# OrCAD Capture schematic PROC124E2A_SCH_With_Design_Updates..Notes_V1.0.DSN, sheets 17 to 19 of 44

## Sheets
17 14. SOC POWER: size C; title: SOC POWER
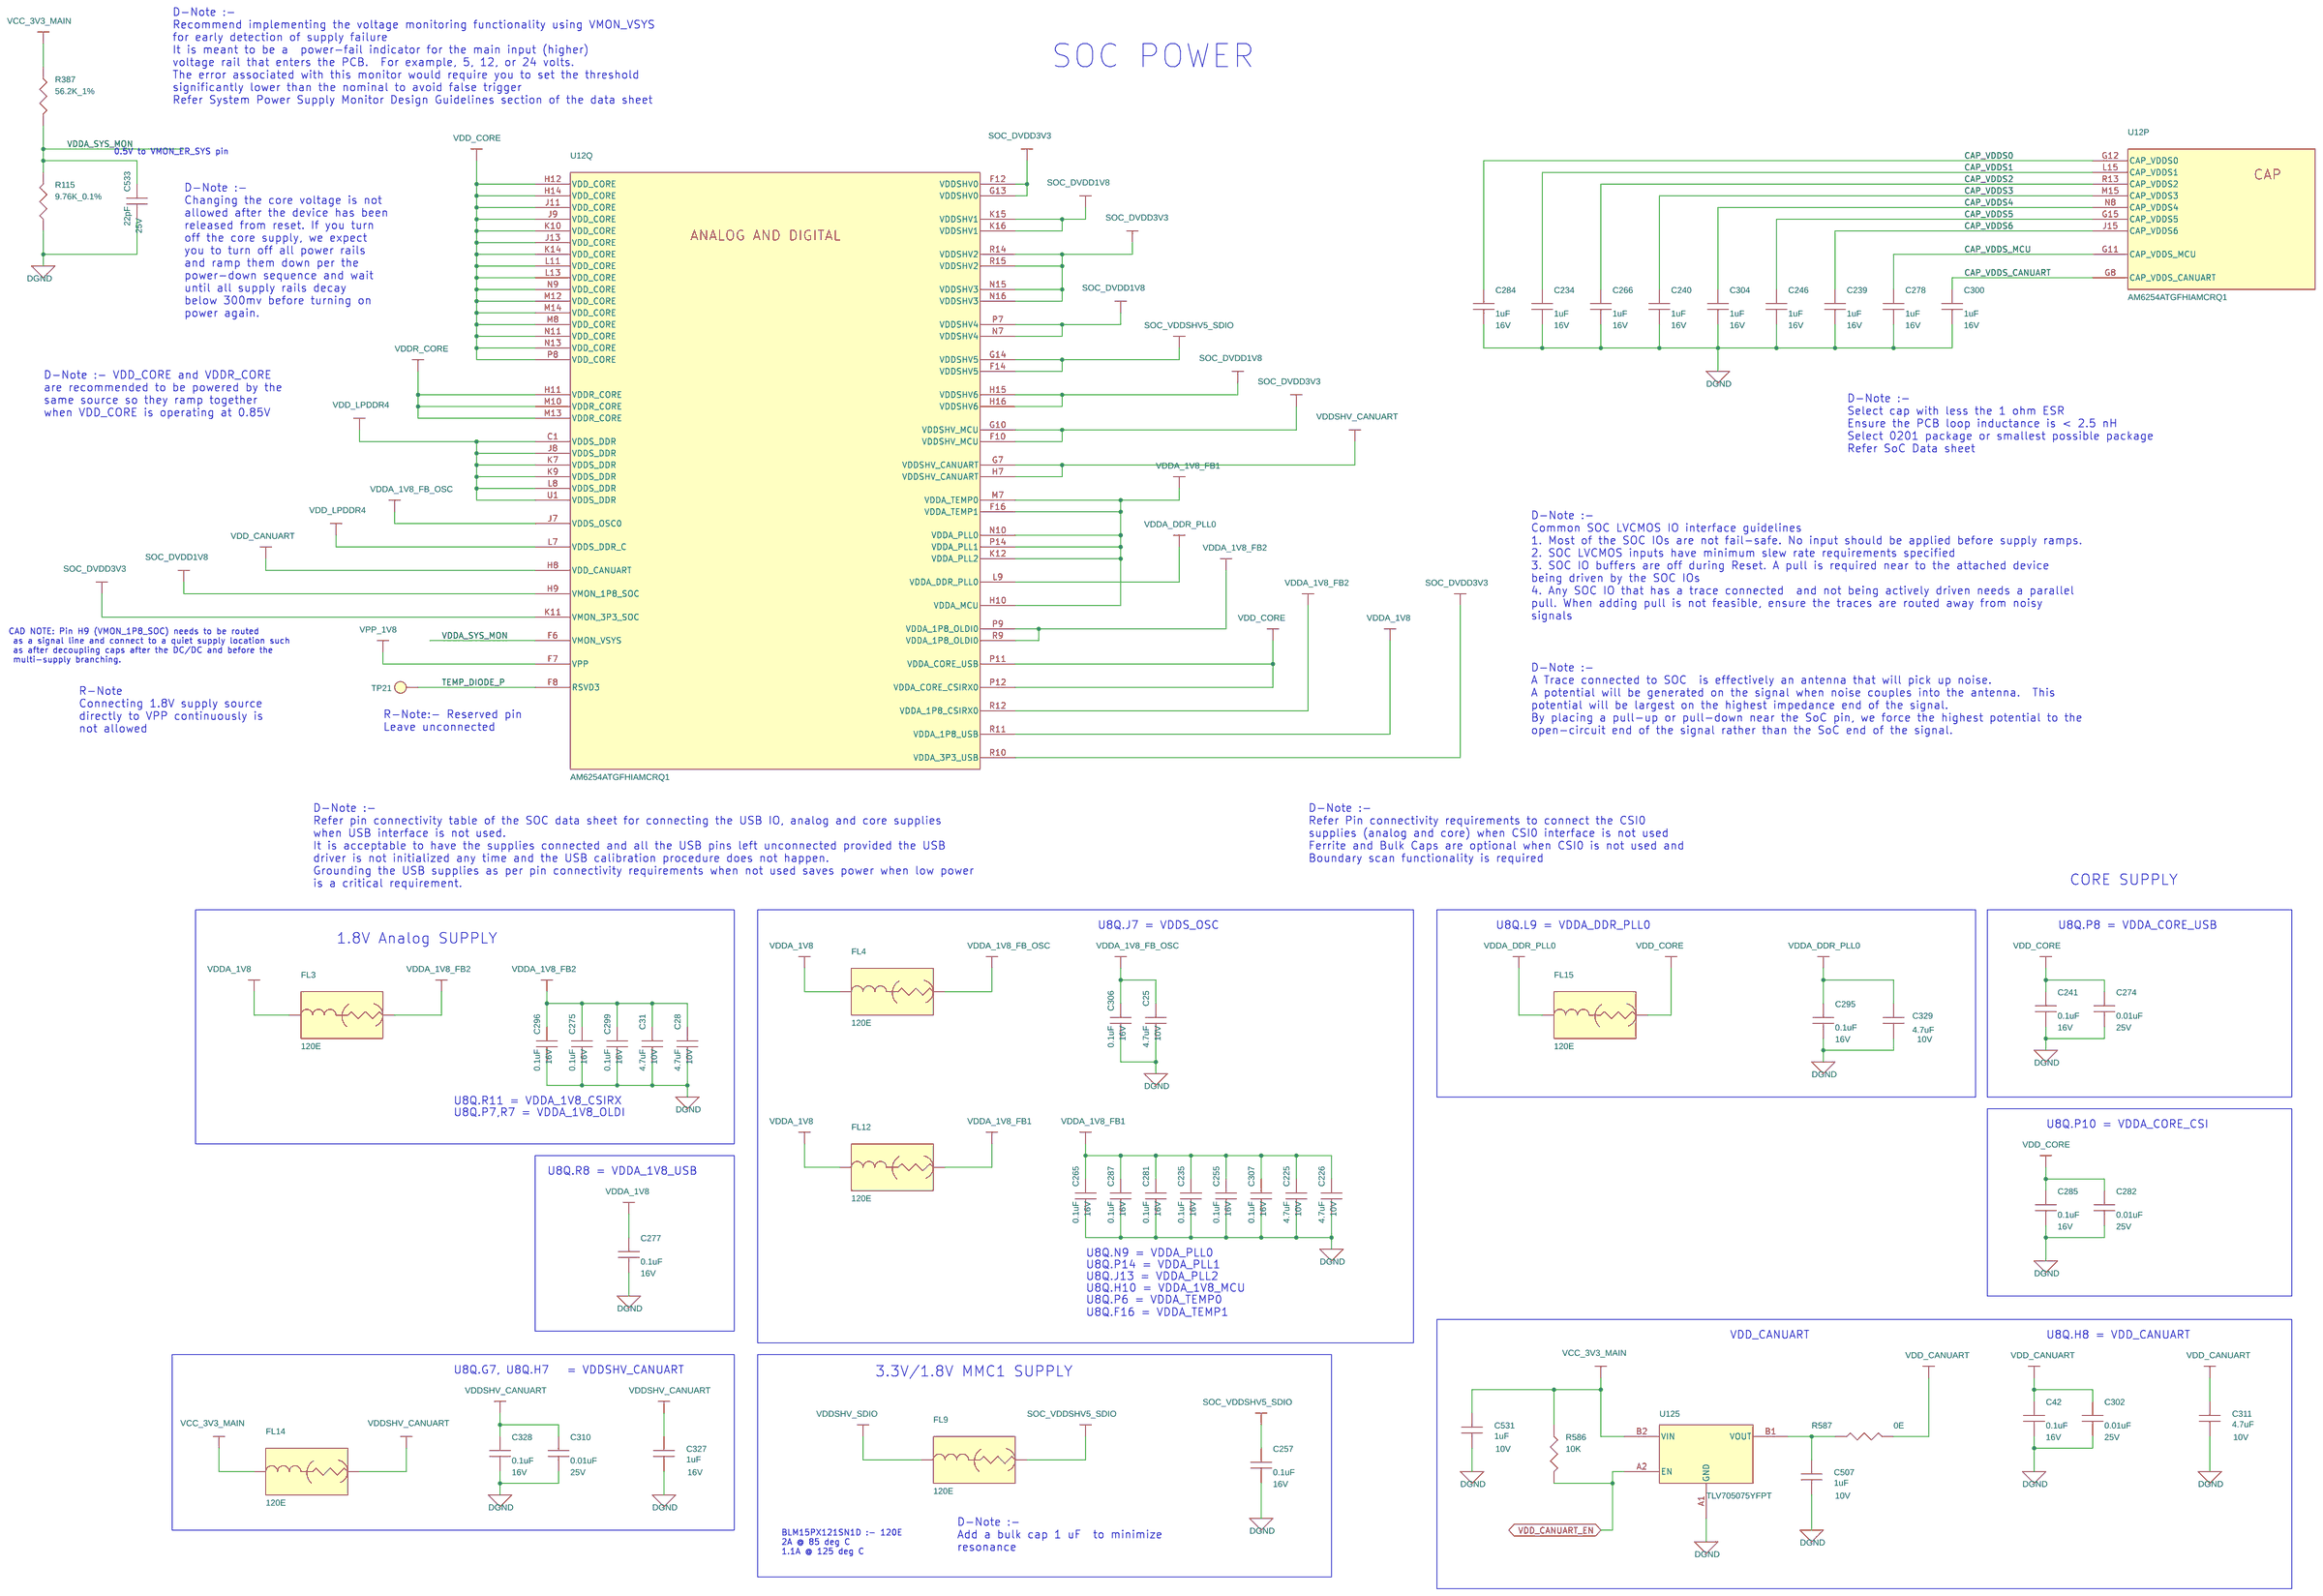
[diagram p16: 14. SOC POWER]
18 15. SOC POWER CAPS: size C; title: SOC POWER CAPS & SOC VSS
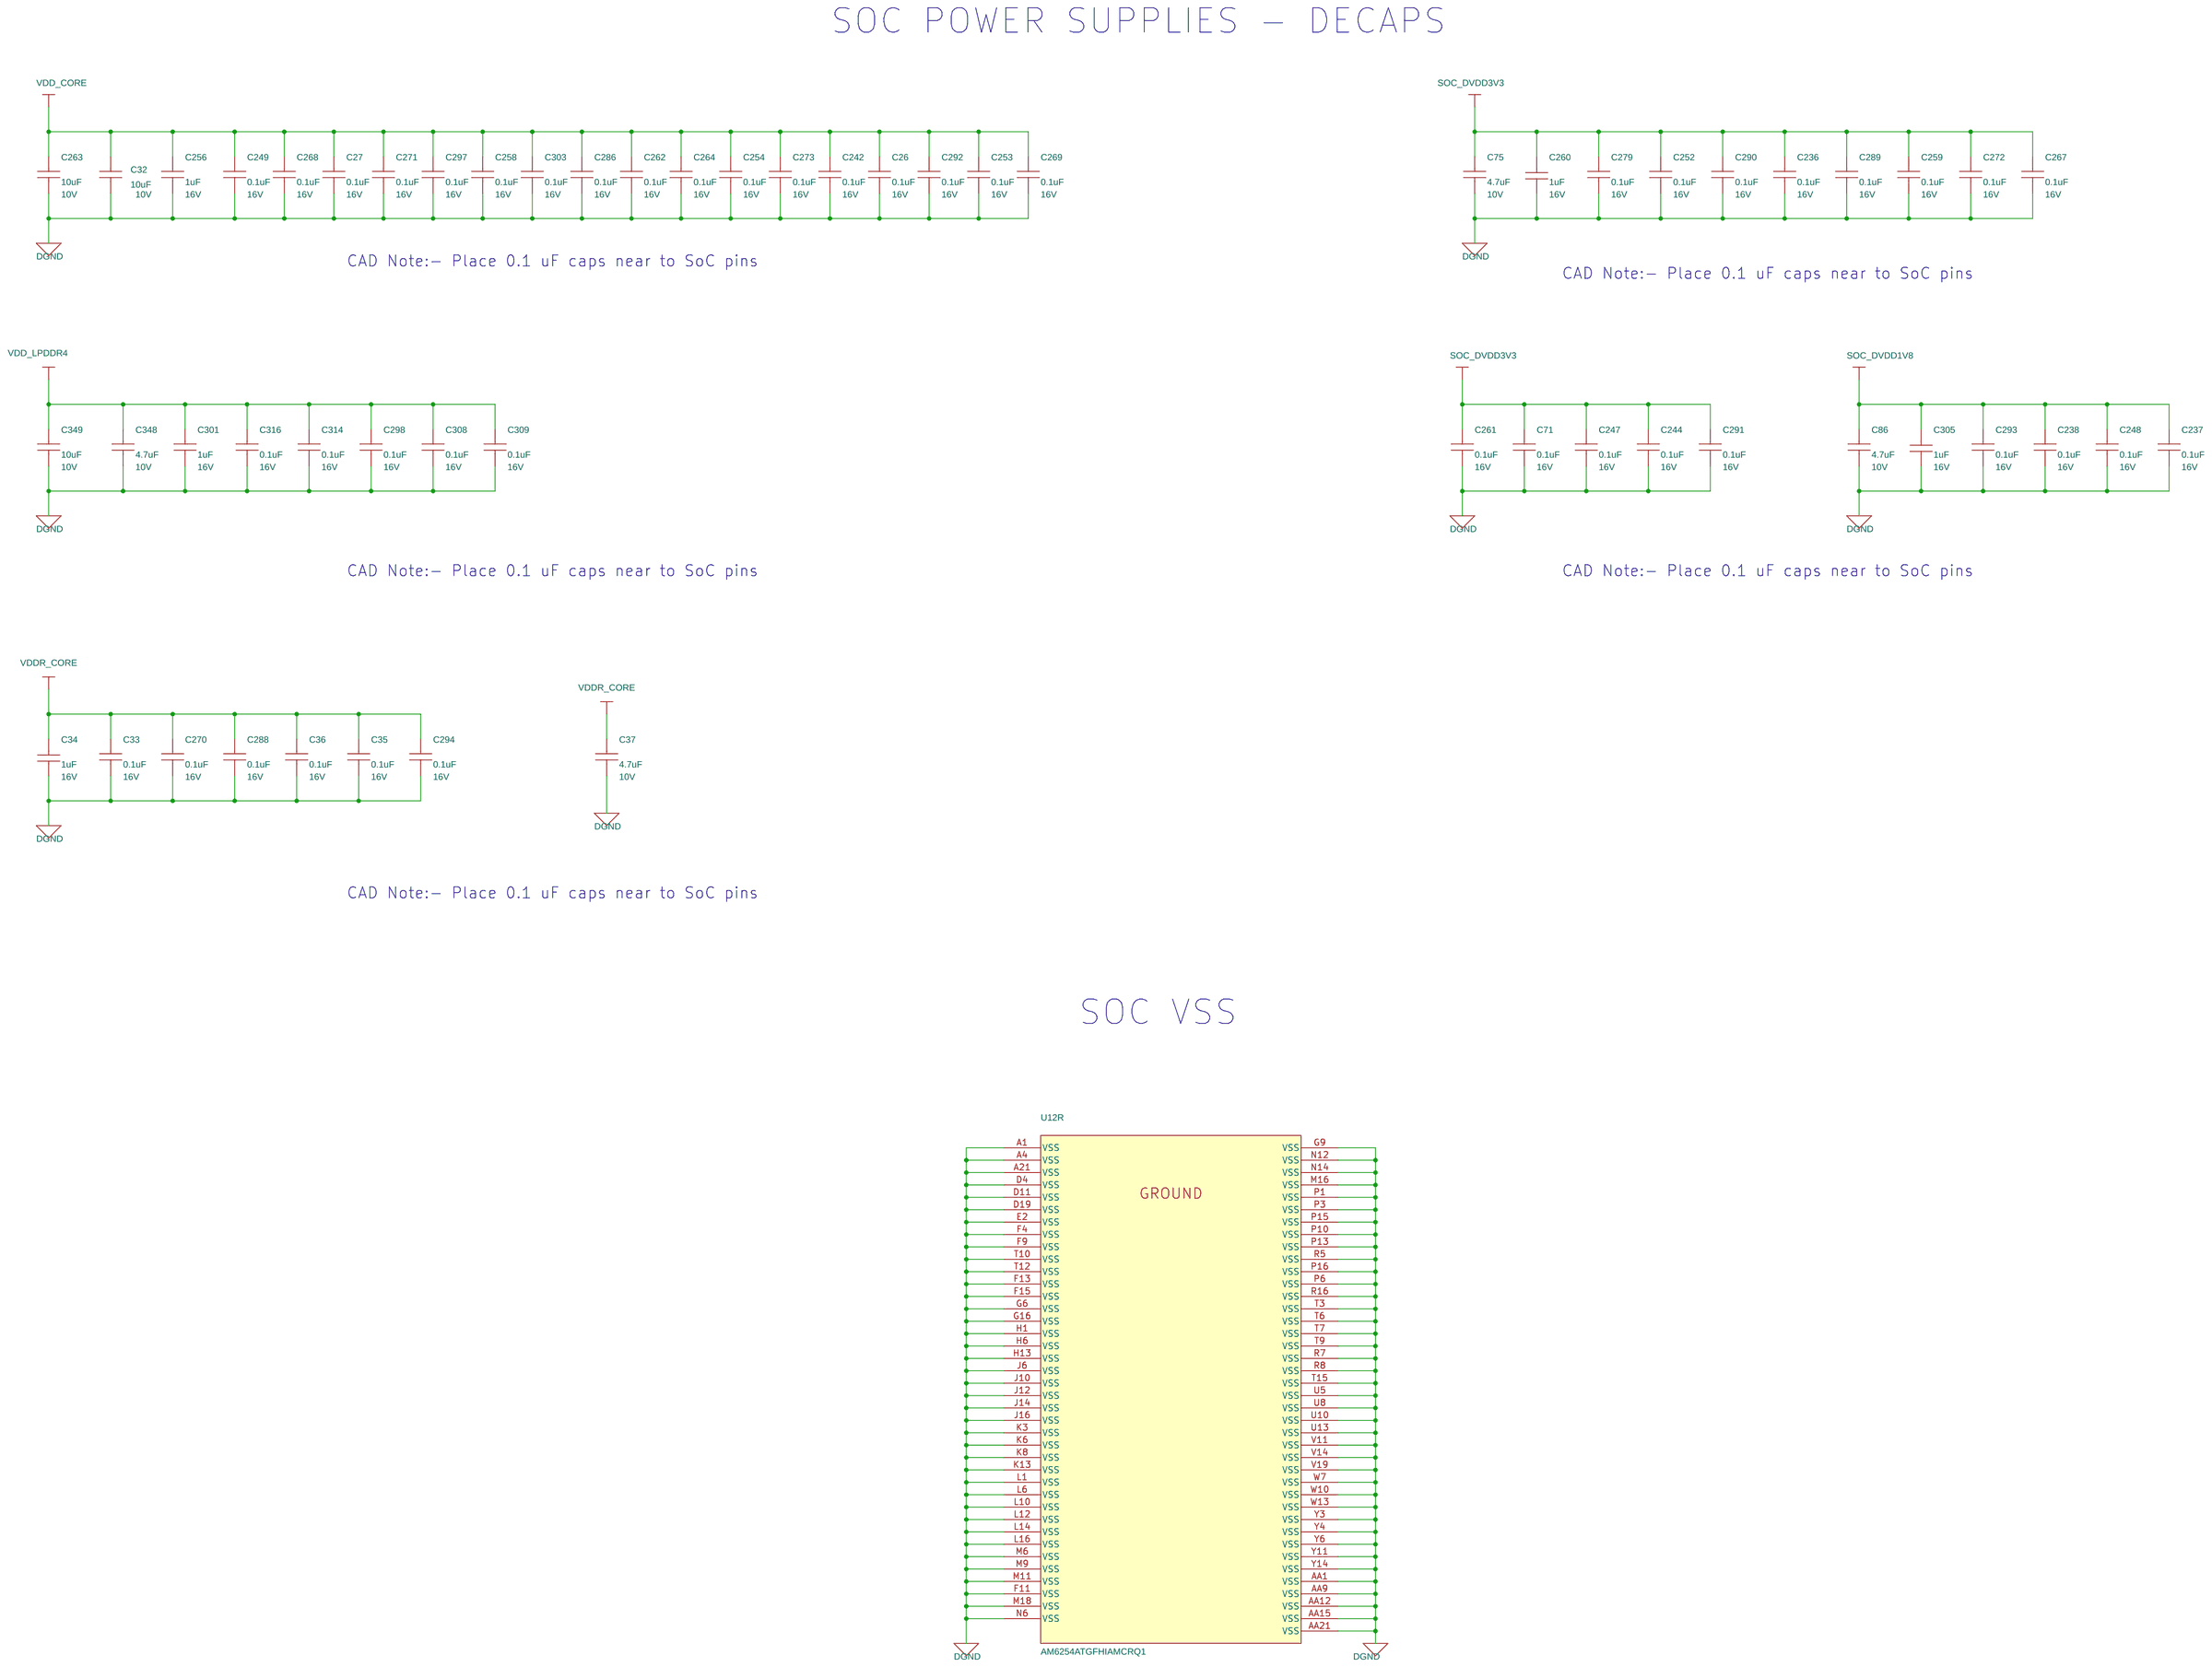
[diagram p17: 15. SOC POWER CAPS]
19 17. M.2 CONNECTOR: size C; title: M.2 CONNECTOR I/F
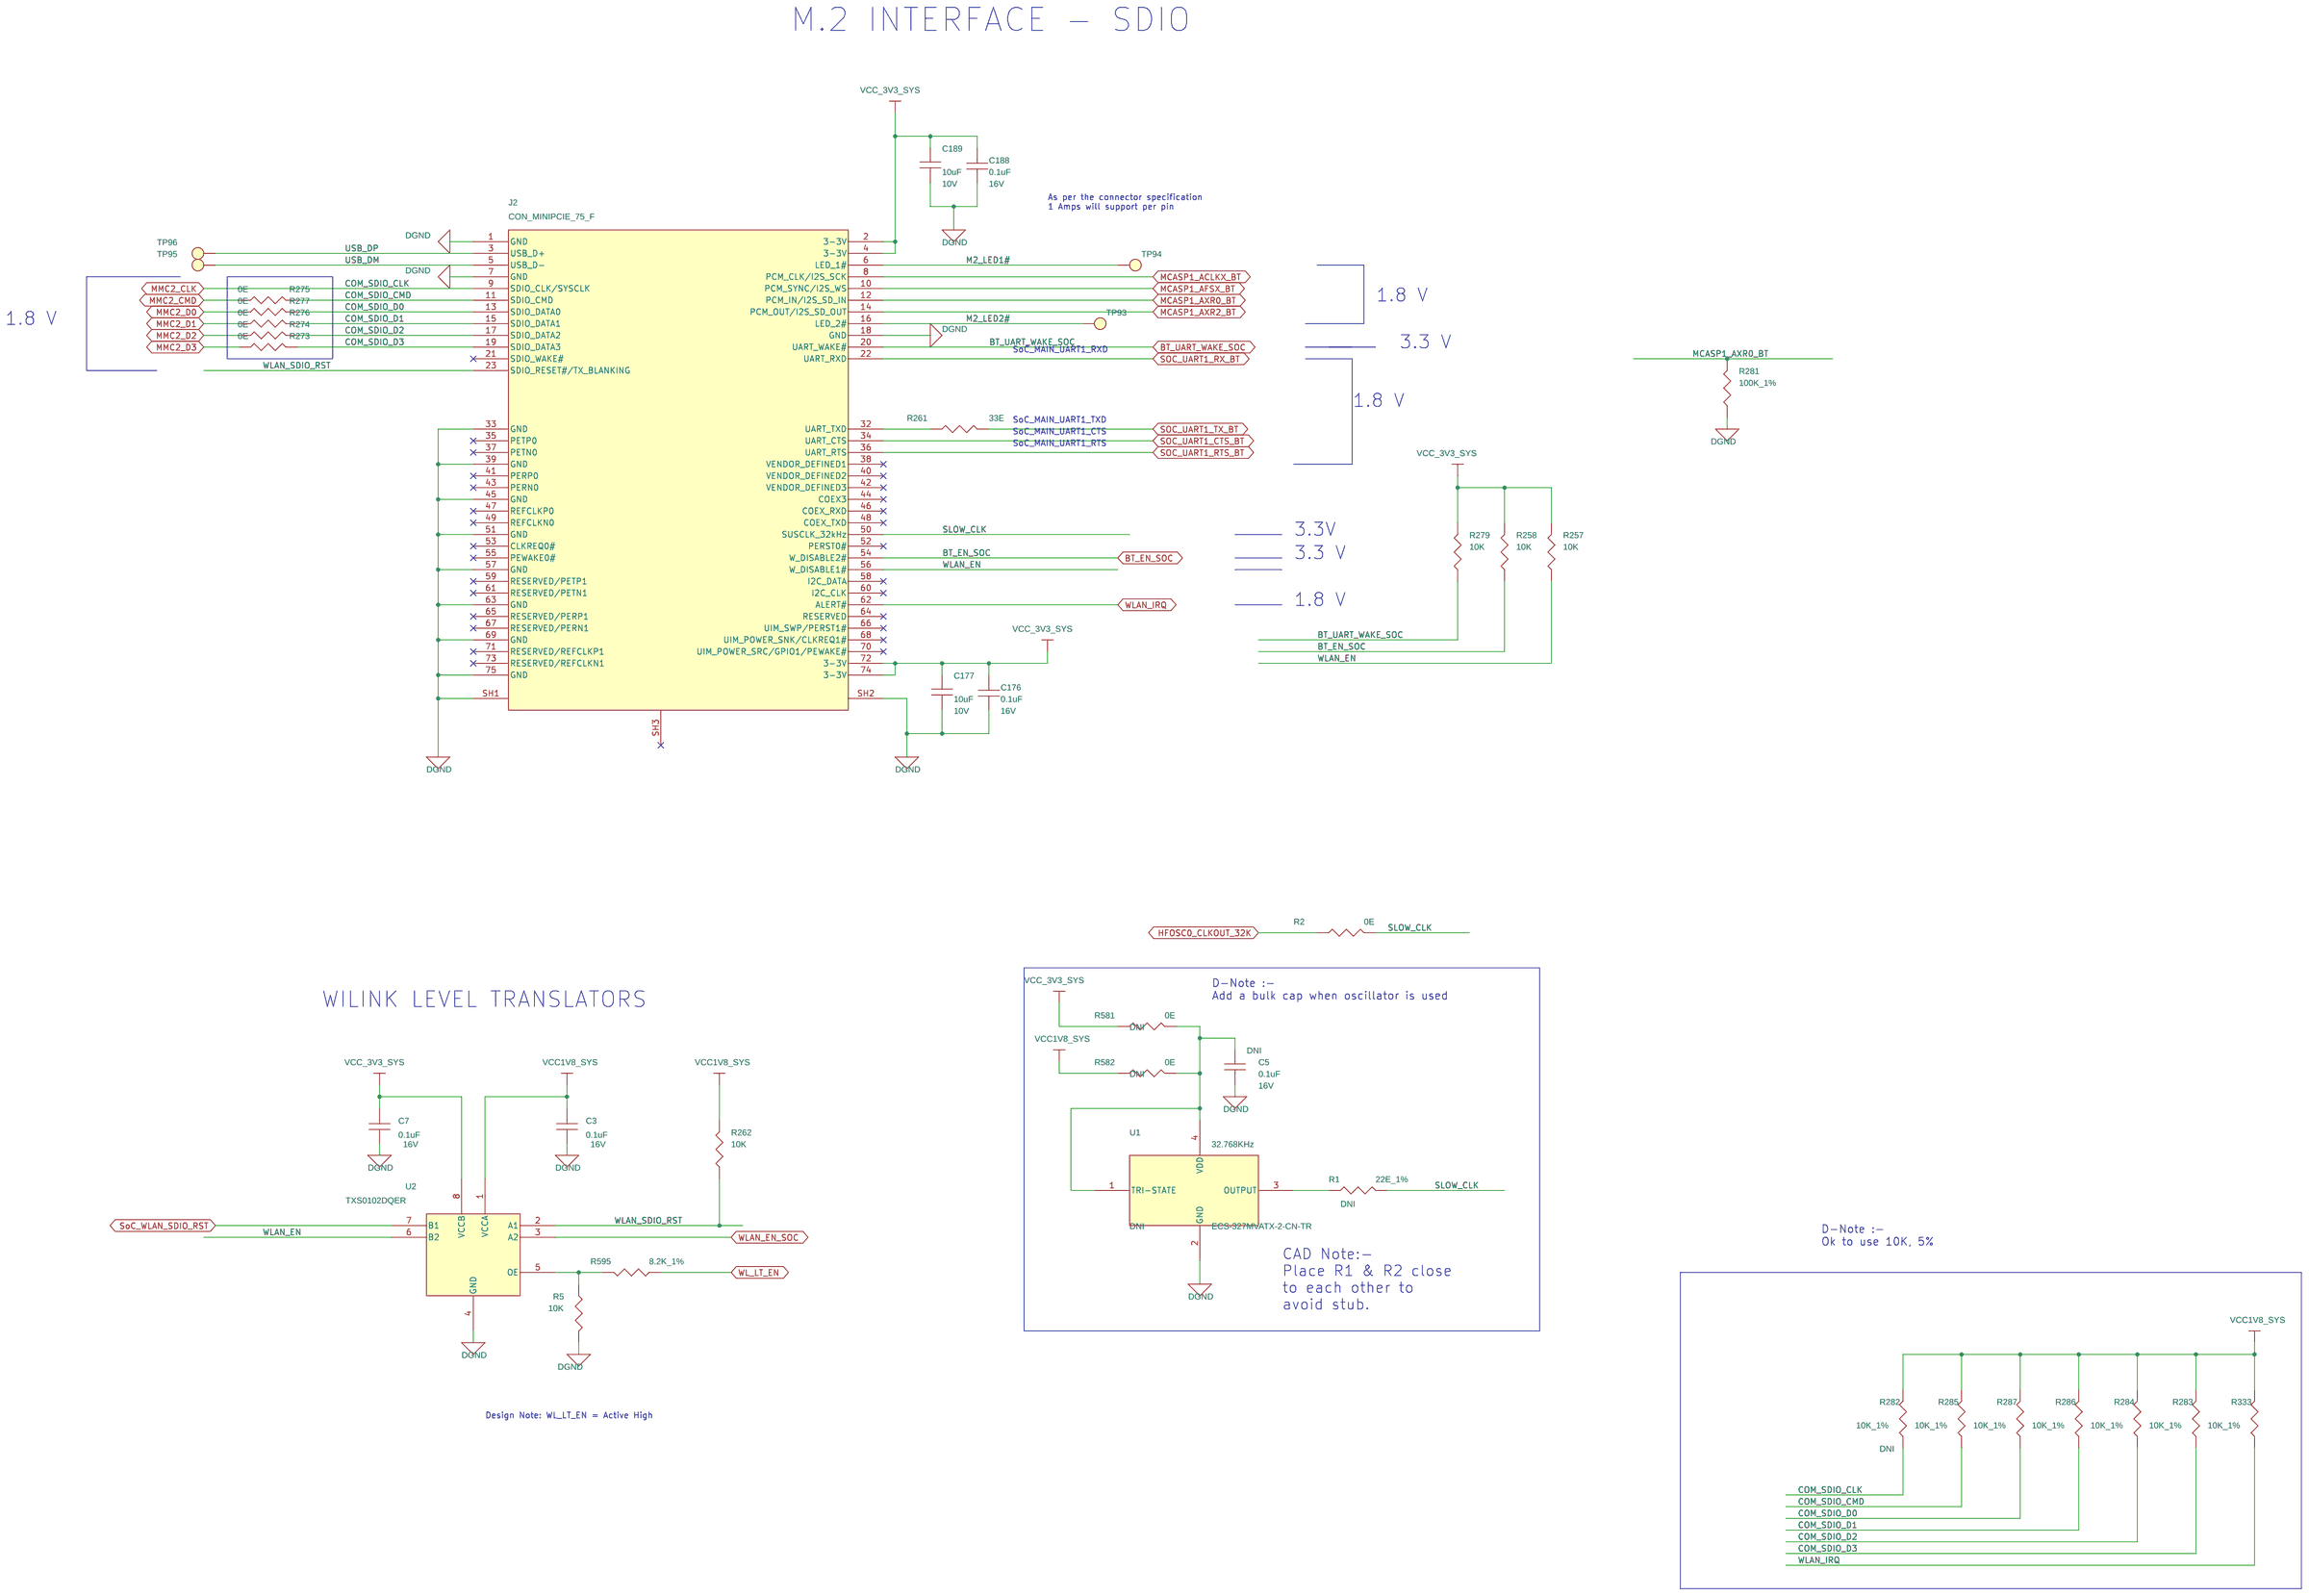
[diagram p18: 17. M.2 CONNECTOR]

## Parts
sheet 14. SOC POWER
C25  4.7uF  [CAP0402_0-75]
C28  4.7uF  [CAP0402_0-75]
C31  4.7uF  [CAP0402_0-75]
C42  0.1uF  [CAP0201_0-5]
C225  4.7uF  [CAP0402_0-75]
C226  4.7uF  [CAP0402_0-75]
C234  1uF  [CAP0201_0-5]
C235  0.1uF  [CAP0201_0-5]
C239  1uF  [CAP0201_0-5]
C240  1uF  [CAP0201_0-5]
C241  0.1uF  [CAP0201_0-5]
C246  1uF  [CAP0201_0-5]
C255  0.1uF  [CAP0201_0-5]
C257  0.1uF  [CAP0201_0-5]
C265  0.1uF  [CAP0201_0-5]
C266  1uF  [CAP0201_0-5]
C274  0.01uF  [CAP0201_0-5]
C275  0.1uF  [CAP0201_0-5]
C277  0.1uF  [CAP0201_0-5]
C278  1uF  [CAP0201_0-5]
C281  0.1uF  [CAP0201_0-5]
C282  0.01uF  [CAP0201_0-5]
C284  1uF  [CAP0201_0-5]
C285  0.1uF  [CAP0201_0-5]
C287  0.1uF  [CAP0201_0-5]
C295  0.1uF  [CAP0201_0-5]
C296  0.1uF  [CAP0201_0-5]
C299  0.1uF  [CAP0201_0-5]
C300  1uF  [CAP0201_0-5]
C302  0.01uF  [CAP0201_0-5]
C304  1uF  [CAP0201_0-5]
C306  0.1uF  [CAP0201_0-5]
C307  0.1uF  [CAP0201_0-5]
C310  0.01uF  [CAP0201_0-5]
C311  4.7uF  [CAP0402_0-75]
C327  1uF  [CAP0201_0-5]
C328  0.1uF  [CAP0201_0-5]
C329  4.7uF  [CAP0402_0-75]
C507  1uF  [CAP0201_0-5]
C531  1uF  [CAP0201_0-5]
C533  22pF  [CAP0201_0-5]
FL3  120E  [EMIFIL_BLM15A_0402_0-6]
FL4  120E  [EMIFIL_BLM15A_0402_0-6]
FL9  120E  [EMIFIL_BLM15A_0402_0-6]
FL12  120E  [EMIFIL_BLM15A_0402_0-6]
FL14  120E  [EMIFIL_BLM15A_0402_0-6]
FL15  120E  [EMIFIL_BLM15A_0402_0-6]
R115  9.76K_0.1%  [RES0402_0-5]
R387  56.2K_1%  [RES0402_0-5]
R586  10K  [RES0201_0-5]
R587  0E  [RES0402_0-5]
TP21  TP20_SMD  [TP20_SMD]
U125  TLV705075YFPT  [DSBGA4_15-74_30X30_0-5]
sheet 15. SOC POWER CAPS
C26  0.1uF  [CAP0201_0-5]
C27  0.1uF  [CAP0201_0-5]
C32  10uF  [CAP0402_0-75]
C33  0.1uF  [CAP0201_0-5]
C34  1uF  [CAP0201_0-5]
C35  0.1uF  [CAP0201_0-5]
C36  0.1uF  [CAP0201_0-5]
C37  4.7uF  [CAP0402_0-75]
C71  0.1uF  [CAP0201_0-5]
C75  4.7uF  [CAP0402_0-75]
C86  4.7uF  [CAP0402_0-75]
C236  0.1uF  [CAP0201_0-5]
C237  0.1uF  [CAP0201_0-5]
C238  0.1uF  [CAP0201_0-5]
C242  0.1uF  [CAP0201_0-5]
C244  0.1uF  [CAP0201_0-5]
C247  0.1uF  [CAP0201_0-5]
C248  0.1uF  [CAP0201_0-5]
C249  0.1uF  [CAP0201_0-5]
C252  0.1uF  [CAP0201_0-5]
C253  0.1uF  [CAP0201_0-5]
C254  0.1uF  [CAP0201_0-5]
C256  1uF  [CAP0201_0-5]
C258  0.1uF  [CAP0201_0-5]
C259  0.1uF  [CAP0201_0-5]
C260  1uF  [CAP0201_0-5]
C261  0.1uF  [CAP0201_0-5]
C262  0.1uF  [CAP0201_0-5]
C263  10uF  [CAP0402_0-75]
C264  0.1uF  [CAP0201_0-5]
C267  0.1uF  [CAP0201_0-5]
C268  0.1uF  [CAP0201_0-5]
C269  0.1uF  [CAP0201_0-5]
C270  0.1uF  [CAP0201_0-5]
C271  0.1uF  [CAP0201_0-5]
C272  0.1uF  [CAP0201_0-5]
C273  0.1uF  [CAP0201_0-5]
C279  0.1uF  [CAP0201_0-5]
C286  0.1uF  [CAP0201_0-5]
C288  0.1uF  [CAP0201_0-5]
C289  0.1uF  [CAP0201_0-5]
C290  0.1uF  [CAP0201_0-5]
C291  0.1uF  [CAP0201_0-5]
C292  0.1uF  [CAP0201_0-5]
C293  0.1uF  [CAP0201_0-5]
C294  0.1uF  [CAP0201_0-5]
C297  0.1uF  [CAP0201_0-5]
C298  0.1uF  [CAP0201_0-5]
C301  1uF  [CAP0201_0-5]
C303  0.1uF  [CAP0201_0-5]
C305  1uF  [CAP0201_0-5]
C308  0.1uF  [CAP0201_0-5]
C309  0.1uF  [CAP0201_0-5]
C314  0.1uF  [CAP0201_0-5]
C316  0.1uF  [CAP0201_0-5]
C348  4.7uF  [CAP0402_0-75]
C349  10uF  [CAP0402_0-75]
U12  AM6254ATGFHIAMCRQ1  [FCBGA441_31-49_680X680_2-6]  (sections A,B,C,D,E,F,G,H,I,J,K,L,M,N,O,P,Q,R)
sheet 17. M.2 CONNECTOR
C3  0.1uF  [CAP0201_0-5]
C5  0.1uF  [CAP0201_0-5]
C7  0.1uF  [CAP0201_0-5]
C176  0.1uF  [CAP0201_0-5]
C177  10uF  [CAP0402_0-75]
C188  0.1uF  [CAP0201_0-5]
C189  10uF  [CAP0402_0-75]
J2  CON_MINIPCIE_75_F  [CON_MINIPCI75_2199119-4_S_R_S_3-2_2230]
R1  22E_1%  [RES0201_0-5]
R2  0E  [RES0201_0-5]
R5  10K  [RES0201_0-5]
R257  10K  [RES0201_0-5]
R258  10K  [RES0201_0-5]
R261  33E  [RES0201_0-5]
R262  10K  [RES0201_0-5]
R273  0E  [RES0201_0-5]
R274  0E  [RES0201_0-5]
R275  0E  [RES0201_0-5]
R276  0E  [RES0201_0-5]
R277  0E  [RES0201_0-5]
R279  10K  [RES0201_0-5]
R281  100K_1%  [RES0402_0-5]
R282  10K_1%  [RES0201_0-5]
R283  10K_1%  [RES0201_0-5]
R284  10K_1%  [RES0201_0-5]
R285  10K_1%  [RES0201_0-5]
R286  10K_1%  [RES0201_0-5]
R287  10K_1%  [RES0201_0-5]
R333  10K_1%  [RES0201_0-5]
R581  0E  [RES0201_0-5]
R582  0E  [RES0201_0-5]
R595  8.2K_1%  [RES0201_0-5]
TP93  TP20_SMD  [TP20_SMD]
TP94  TP20_SMD  [TP20_SMD]
TP95  TP20_SMD  [TP20_SMD]
TP96  TP20_SMD  [TP20_SMD]
U1  32.768KHz  [OSC4_ECS-327MVATX-2_100X80_SMD_1]
U2  TXS0102DQER  [X2SON8_TXS0102_40X60_0-4]

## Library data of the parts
C25 C28 C31 C37 C75 C86 C225 C226 C311 C329 C348 = CAP: CAP CERAMIC 4.7uF 10V 20% X5R 0402; Chkd/date: MANIRAJA/110718; Crtd /date: ALVY/110718; Custom_Duty: 15%; Customs_HS_Code: 85322990; Distributor_name: DIGIKEY; Distributor_part_number: 490-14306-1-ND; Footprint Path: Y:\MIS_DATABASE\Library\ALTIUM_TOOL\PCB_FOOTPRINTS\Altium_Footprint_Lib.PcbLib; Height: 0.65MM; Library Path: Y:\MIS_DATABASE\Library\ALTIUM_TOOL\SCHEMATICS_PARTS\MS_DISCRETE_Library.schlib; Mfr_name: MURATA; Mfr_part_number: GRM155R61A475MEAAD; Mistral Part No: 120012060002-R; Package: 0402; Part_type: CAPACITORS\CERAMIC; Project: TI_J7SVB_PCIE_ADD-ON-CARD; RoHS: RoHS; Temperature: -55°C+85°C; Tolerance: 20%; Voltage: 10V; Wattage: NA; Weight: 14mg; Datasheet: Y:\MIS_DATABASE\DATASHEETS\CAPACITORS\GRM155R61A475MEAAD.PDF
C26 C27 C33 C35 C36 C42 C71 C235-C238 C241 C242 C244 C247-C249 C252-C255 C257-C259 C261 C262 C264 C265 C267-C273 C275 C277 C279 C281 C285-C299 C303 C306-C309 C314 C316 C328 = CAP: CAP CERAMIC 0.1uF 16V 10% X5R 0201; Chkd/date: MANIRAJA/230118; Crtd /date: MANIRAJA/230118; Custom_Duty: 15%; Customs_HS_Code: 85322990; Distributor_name: DIGIKEY; Distributor_part_number: 490-14305-1-ND; Footprint Path: Y:\MIS_DATABASE\Library\ALTIUM_TOOL\PCB_FOOTPRINTS\Altium_Footprint_Lib.PcbLib; Height: 0.33MM; Library Path: Y:\MIS_DATABASE\Library\ALTIUM_TOOL\SCHEMATICS_PARTS\MS_DISCRETE_Library.schlib; Mfr_name: MURATA; Mfr_part_number: GRM033R61C104KE14D; Mistral Part No: 120009030072-R; Package: 0201; Part_type: CAPACITORS\CERAMIC; Project: TI_MAXIE_CPB; RoHS: RoHS; Temperature: -55°C+85°C; Tolerance: 10%; Voltage: 16V; Wattage: NA; Weight: 0.33mg; Datasheet: Y:\MIS_DATABASE\DATASHEETS\CAPACITORS\GRM033R61C104KE14.PDF
C34 C234 C239 C240 C246 C256 C260 C266 C278 C284 C300 C301 C304 C305 C327 = CAP: CAP CERAMIC 1uF 16V 20% X5R 0201; Chkd/date: MANIRAJA/300520; Crtd /date: ALVY/260520; Custom_Duty: 15%; Customs_HS_Code: 85322990; Distributor_name: DIGIKEY; Distributor_part_number: 490-18654-1-ND; Footprint Path: Y:\MIS_DATABASE\Library\ALTIUM_TOOL\PCB_FOOTPRINTS\Altium_Footprint_Lib.PcbLib; Height: 0.39MM; Library Path: Y:\MIS_DATABASE\Library\ALTIUM_TOOL\SCHEMATICS_PARTS\MS_DISCRETE_Library.schlib; Mfr_name: MURATA; Mfr_part_number: GRM033R61C105ME15D; Mistral Part No: 120018090038-R; Package: 0201; Part_type: CAPACITORS\CERAMIC; Project: QCS610_NANOSOM; RoHS: RoHS; Temperature: -55°C+85°C; Tolerance: 20%; Voltage: 16V; Wattage: NA; Weight: 0.33mg; Datasheet: Y:\MIS_DATABASE\DATASHEETS\CAPACITORS\GRM033R61C105ME15.PDF
C274 C282 C302 C310 = CAP: CAP CERAMIC 0.01uF 25V 10% X5R 0201; Chkd/date: MANIRAJA/230118; Crtd /date: MANIRAJA/230118; Custom_Duty: 15%; Customs_HS_Code: 85322990; Distributor_name: DIGIKEY; Distributor_part_number: GRM033R61E103KA12J-ND; Footprint Path: Y:\MIS_DATABASE\Library\ALTIUM_TOOL\PCB_FOOTPRINTS\Altium_Footprint_Lib.PcbLib; Height: 0.33MM; Library Path: Y:\MIS_DATABASE\Library\ALTIUM_TOOL\SCHEMATICS_PARTS\MS_DISCRETE_Library.schlib; Mfr_name: MURATA; Mfr_part_number: GRM033R61E103KA12J; Mistral Part No: 120018010007-R; Package: 0201; Part_type: CAPACITORS\CERAMIC; Project: TI_MAXIE_CPB; RoHS: RoHS; Temperature: -55°C+85°C; Tolerance: 10%; Voltage: 25V; Wattage: NA; Weight: 0.33mg; Datasheet: Y:\MIS_DATABASE\DATASHEETS\CAPACITORS\GRM033R61E103KA12.PDF
C507 C531 = CAP: CAP CERAMIC 1uF 10V 20% X5R 0201; Chkd/date: NAVEED/070415; Crtd /date: VASANTHA/230314; Custom_Duty: 15%; Customs_HS_Code: 85322990; Distributor_name: DIGIKEY; Distributor_part_number: 1276-1324-1-ND; Footprint Path: Y:\MIS_DATABASE\Library\ALTIUM_TOOL\PCB_FOOTPRINTS\Altium_Footprint_Lib.PcbLib; Height: 0.35MM; Library Path: Y:\MIS_DATABASE\Library\ALTIUM_TOOL\SCHEMATICS_PARTS\MS_DISCRETE_Library.schlib; Mfr_name: SAMSUNG; Mfr_part_number: CL03A105MP3NSNC; Mistral Part No: 120015030003-R; Package: 0201; Part_type: CAPACITORS\CERAMIC; Project: DUET BOARDS; RoHS: RoHS; Temperature: -55°C+85°C; Tolerance: 20%; Voltage: 10V; Wattage: NA; Weight: 0.17mg; Datasheet: Y:\MIS_DATABASE\DATASHEETS\CAPACITORS\CL03A105MP3NSNC.PDF
C533 = CAP: CAP CERAMIC 22pF 25V 1% C0G(NP0) 0201; Chkd/date: MANIRAJA/270721; Crtd /date: ALVY/260721; Custom_Duty: 15%; Customs_HS_Code: 85322990; Distributor_name: DIGIKEY; Distributor_part_number: 490-14545-1-ND; Footprint Path: Y:\MIS_DATABASE\Library\ALTIUM_TOOL\PCB_FOOTPRINTS\Altium_Footprint_Lib.PcbLib; Height: 0.33MM; Library Path: Y:\MIS_DATABASE\Library\ALTIUM_TOOL\SCHEMATICS_PARTS\MS_DISCRETE_Library.schlib; Mfr_name: MURATA; Mfr_part_number: GRM0335C1E220FA01D; Mistral Part No: 120021070019-R; Package: 0201; Part_type: CAPACITORS\CERAMIC; Project: TI_AM335x SK_BRD; RoHS: RoHS; Temperature: -55°C+125°C; Tolerance: 1%; Voltage: 25V; Wattage: NA; Weight: 0.33mg; Datasheet: Y:\MIS_DATABASE\DATASHEETS\CAPACITORS\GRM0335C1E220FA01.PDF
FL3 FL4 FL9 FL12 FL14 FL15 = EMIFILTER_IND: IND FERRITE BEAD CHIP 120E 2A 0402; Chkd/date: NAVEED/241114; Crtd /date: USMAN/170613; Custom_Duty: 24%; Customs_HS_Code: 85369090; Distributor_name: DIGIKEY; Distributor_part_number: 490-9656-1-ND; Footprint Path: Y:\MIS_DATABASE\Library\ALTIUM_TOOL\PCB_FOOTPRINTS\Altium_Footprint_Lib.PcbLib; Height: 0.55MM; Library Path: Y:\MIS_DATABASE\Library\ALTIUM_TOOL\SCHEMATICS_PARTS\MS_FILTER_Library.schlib; Mfr_name: MURATA; Mfr_part_number: BLM15PX121SN1D; Mistral Part No: 130013060022-R; Package: 0402; Part_type: INDUCTOR; Project: GEN_3-8; RoHS: RoHS; Temperature: -55°C+125°C; Tolerance: 25%; Voltage: NA; Wattage: NA; Weight: 1mg; Datasheet: Y:\MIS_DATABASE\DATASHEETS\DISCRETES\INDUCTORS\BLM15-SN1-SER.PDF
R115 = RESISTOR: RES 9.76K 1/16W 0.1% 0402; Chkd/date: MANIRAJA/190419; Crtd /date: MANIRAJA/190419; Custom_Duty: 15%; Customs_HS_Code: 85332119; Distributor_name: DIGIKEY; Distributor_part_number: P9.76KDCCT-ND; Footprint Path: Y:\MIS_DATABASE\Library\ALTIUM_TOOL\PCB_FOOTPRINTS\Altium_Footprint_Lib.PcbLib; Height: 0.40MM; Library Path: Y:\MIS_DATABASE\Library\ALTIUM_TOOL\SCHEMATICS_PARTS\MS_DISCRETE_Library.schlib; Manufacturer: VISHAY; Mfr_name: PANASONIC-ECG; Mfr_part_number: ERA-2AEB9761X; Mistral Part No: 110019040291-R; Package: 0402; Part_type: RESISTORS\FIXED; Project: TI_J7ES_EVM_FUSION2_SER_CAP; RoHS: RoHS; Temperature: -55°C+155°C; Tolerance: 0.1%; Voltage: NA; Wattage: 1/16W; Weight: 0.6mg; Datasheet: Y:\MIS_DATABASE\DATASHEETS\RESISTORS\ERA-1A.PDF
R387 = RESISTOR: RES 56.2K 1/16W 1% 0402; Chkd/date: PRAVEEN/090922; Crtd /date: TAMILARASU/090922; Custom_Duty: 15%; Customs_HS_Code: 85332119; Distributor_name: DIGIKEY; Distributor_part_number: RMCF0402FT56K2CT-ND; Footprint Path: Y:\MIS_DATABASE\Library\ALTIUM_TOOL\PCB_FOOTPRINTS\Altium_Footprint_Lib.PcbLib; Height: 0.40MM; Library Path: Y:\MIS_DATABASE\Library\ALTIUM_TOOL\SCHEMATICS_PARTS\MS_DISCRETE_Library.schlib; Mfr_name: STACKPOLE ELECTRONICS; Mfr_part_number: RMCF0402FT56K2; Mistral Part No: 110022090013-R; Package: 0402; Part_type: RESISTORS\FIXED; Project: SK AM62Q LP EVM BRD; RoHS: RoHS; Temperature: -55°C+155°C; Tolerance: 1%; Voltage: NA; Wattage: 1/16W; Weight: NA; Datasheet: Y:\MIS_DATABASE\DATASHEETS\RESISTORS\RMCF-SER_JUL18.PDF
R5 R257 R258 R262 R279 R586 = RESISTOR: RES 10K 1/20W 5% 0201; Chkd/date: MANIRAJA/050517; Crtd /date: MANIRAJA/050517; Custom_Duty: 15%; Customs_HS_Code: 85332119; Distributor_name: DIGIKEY; Distributor_part_number: 311-10KNCT-ND; Footprint Path: Y:\MIS_DATABASE\Library\ALTIUM_TOOL\PCB_FOOTPRINTS\Altium_Footprint_Lib.PcbLib; Height: 0.26MM; Library Path: Y:\MIS_DATABASE\Library\ALTIUM_TOOL\SCHEMATICS_PARTS\MS_DISCRETE_Library.schlib; Mfr_name: YAGEO AMERICA; Mfr_part_number: RC0201JR-0710KL; Mistral Part No: 110010070051-R; Package: 0201; Part_type: RESISTORS\FIXED; Project: GOLDEN-I LITE; RoHS: RoHS; Temperature: -55°C+125°C; Tolerance: 5%; Voltage: NA; Wattage: 1/20W; Weight: 0.17mg; Datasheet: Y:\MIS_DATABASE\DATASHEETS\RESISTORS\RCXXXXL-SER_MAR18.PDF
R587 = RESISTOR: RES 0E 1/10W JUMPER 0402; Chkd/date: VASANTHA/061216; Crtd /date: NAVEED/201014; Custom_Duty: 15%; Customs_HS_Code: 85332119; Distributor_name: DIGIKEY; Distributor_part_number: P0.0JCT-ND; Footprint Path: Y:\MIS_DATABASE\Library\ALTIUM_TOOL\PCB_FOOTPRINTS\Altium_Footprint_Lib.PcbLib; Height: 0.40MM; IBISSP_MODLES: VALUE REPEATING 2 TIME; Library Path: Y:\MIS_DATABASE\Library\ALTIUM_TOOL\SCHEMATICS_PARTS\MS_DISCRETE_Library.schlib; Mfr_name: PANASONIC-ECG; Mfr_part_number: ERJ-2GE0R00X; Mistral Part No: 110018030052-R; Package: 0402; Part_type: RESISTORS\FIXED; Project: AEGIS POM; RoHS: RoHS; Temperature: -55°C+155°C; Tolerance: NA; Voltage: NA; Wattage: 1/10W; Weight: 0.8mg; Datasheet: Y:\MIS_DATABASE\DATASHEETS\RESISTORS\PAN-ERJSER_NOV17.PDF
TP21 TP93-TP96 = TESTPOINT: TESTPOINT CIR 20 SMD; Chkd/date: SHREESHAIL/171006; Crtd /date: MAZHAR/171006; Custom_Duty: NA; Customs_HS_Code: NA; Distributor_name: NA; Distributor_part_number: NA; Footprint Path: Y:\MIS_DATABASE\Library\ALTIUM_TOOL\PCB_FOOTPRINTS\Altium_Footprint_Lib.PcbLib; Height: NA; Library Path: Y:\MIS_DATABASE\Library\ALTIUM_TOOL\SCHEMATICS_PARTS\MS_DISCRETE_Library.schlib; MECHANICAL 3D STEP FILE: NA; Mfr_name: LOCAL; Mistral Part No: NA; Package: SMD; Project: BT MODULE_CSRBC04; RoHS: NA; Temperature: NA; Tolerance: NA; Voltage: NA; Wattage: NA; Weight: NA; Datasheet: NA
U125 = TLV7050_DSBGA4: IC 200mA 0.75V LOW IQ LOW-DROPOUT REGULATOR DSBGA4; Chkd/date: ALVY/300522; Crtd /date: TAMILARASU/300522; Custom_Duty: 15%; Customs_HS_Code: 85423100; Distributor_name: DIGIKEY; Distributor_part_number: 296-TLV705075YFPTCT-ND; Footprint Path: Y:\MIS_DATABASE\Library\ALTIUM_TOOL\PCB_FOOTPRINTS\Altium_Footprint_Lib.PcbLib; Height: 0.50MM; Library Path: Y:\MIS_DATABASE\Library\ALTIUM_TOOL\SCHEMATICS_PARTS\MS_MISCPOWER_Library.schlib; Mfr_name: TEXAS INSTRUMENTS; Mistral Part No: 142022050034-R; Package: DSBGA4; Part_type: ICS\POWER\VOLTAGE REGULATOR; Project: TI_AM62A_SK_EVM; RoHS: RoHS; Temperature: -40°C+125°C; Tolerance: NA; Voltage: NA; Wattage: NA; Weight: 200mg; Datasheet: Y:\MIS_DATABASE\DATASHEETS\ICS\POWER\TLV705X.PDF
C32 C177 C189 C263 C349 = CAP: CAP CERAMIC 10uF 10V 20% X5R 0402; Chkd/date: MANIRAJA/300520; Crtd /date: ALVY/260520; Custom_Duty: 15%; Customs_HS_Code: 85322990; Distributor_name: DIGIKEY; Distributor_part_number: 490-GRM155R61A106ME11DTR-ND; Footprint Path: Y:\MIS_DATABASE\Library\ALTIUM_TOOL\PCB_FOOTPRINTS\Altium_Footprint_Lib.PcbLib; Height: 0.55MM; Library Path: Y:\MIS_DATABASE\Library\ALTIUM_TOOL\SCHEMATICS_PARTS\MS_DISCRETE_Library.schlib; Mfr_name: MURATA; Mfr_part_number: GRM155R61A106ME11D; Mistral Part No: 120013110019-R; Package: 0402; Part_type: CAPACITORS\CERAMIC; Project: QCS610_NANOSOM; RoHS: RoHS; Temperature: -55°C+85°C; Tolerance: 20%; Voltage: 10V; Wattage: NA; Weight: 3.1mg; Datasheet: Y:\MIS_DATABASE\DATASHEETS\CAPACITORS\MURATA-GXX-SER_NOV17.PDF
U12 = AM6254ATGFHIAMCRQ1_FCBGA441: IC AM62Q SoC MICROPROCESSOR FCBGA441; Chkd/date: PRADEEP/180324; Crtd /date: TAMILARASU/180324; Custom_Duty: 15%; Customs_HS_Code: 85423100; Distributor_name: NA; Distributor_part_number: NA; Footprint Path: Y:\MIS_DATABASE\Library\ALTIUM_TOOL\PCB_FOOTPRINTS\Altium_Footprint_Lib.PcbLib; Height: 2.57MM; Library Path: Y:\MIS_DATABASE\Library\ALTIUM_TOOL\SCHEMATICS_PARTS\MS_MICROPROCESSOR_Library.schlib; Mfr_name: TEXAS INSTRUMENTS; Mistral Part No: 141224030001-R; Package: FCBGA441; Part_type: ICS\DIGITAL\MICROPROCESSOR; Project: TI_AM62Q_BRD; RoHS: NA; Temperature: NA; Tolerance: NA; Voltage: NA; Wattage: NA; Weight: NA; Datasheet: Y:\MIS_DATABASE\DATASHEETS\ICS\DIGITAL\MICROCONTROLLER\AM62Q-SoC.PDF
C3 C7 C176 C188 = CAP: CAP CERAMIC 0.1uF 16V 10% X5R 0201; Alt_Mfr_name: YAGEO AMERICA; Alt_Mfr_part_number: CC0402KRX5R8BB104; Chkd/date: MANIRAJA/230118; Crtd /date: MANIRAJA/230118; Custom_Duty: 15%; Customs_HS_Code: 85322990; Distributor_name: DIGIKEY; Distributor_part_number: 490-14305-1-ND; Footprint Path: Y:\MIS_DATABASE\Library\ALTIUM_TOOL\PCB_FOOTPRINTS\Altium_Footprint_Lib.PcbLib; Height: 0.33MM; Library Path: Y:\MIS_DATABASE\Library\ALTIUM_TOOL\SCHEMATICS_PARTS\MS_DISCRETE_Library.schlib; Mfr_name: MURATA; Mfr_part_number: GRM033R61C104KE14D; Mistral Part No: 120009030072-R; Package: 0201; Part_type: CAPACITORS\CERAMIC; Project: TI_MAXIE_CPB; RoHS: RoHS; Temperature: -55°C+85°C; Tolerance: 10%; Voltage: 16V; Wattage: NA; Weight: 0.33mg; Datasheet: Y:\MIS_DATABASE\DATASHEETS\CAPACITORS\GRM033R61C104KE14.PDF
C5 = CAP: CAP CERAMIC 0.1uF 16V 10% X5R 0201; Alt_Mfr_name: YAGEO AMERICA; Alt_Mfr_part_number: CC0402KRX5R8BB104; Assembly_Instruction: DNI; Chkd/date: MANIRAJA/230118; Crtd /date: MANIRAJA/230118; Custom_Duty: 15%; Customs_HS_Code: 85322990; Distributor_name: DIGIKEY; Distributor_part_number: 490-14305-1-ND; Footprint Path: Y:\MIS_DATABASE\Library\ALTIUM_TOOL\PCB_FOOTPRINTS\Altium_Footprint_Lib.PcbLib; Height: 0.33MM; Library Path: Y:\MIS_DATABASE\Library\ALTIUM_TOOL\SCHEMATICS_PARTS\MS_DISCRETE_Library.schlib; Mfr_name: MURATA; Mfr_part_number: GRM033R61C104KE14D; Mistral Part No: 120009030072-R; Package: 0201; Part_type: CAPACITORS\CERAMIC; Project: TI_MAXIE_CPB; RoHS: RoHS; Temperature: -55°C+85°C; Tolerance: 10%; Voltage: 16V; Wattage: NA; Weight: 0.33mg; Datasheet: Y:\MIS_DATABASE\DATASHEETS\CAPACITORS\GRM033R61C104KE14.PDF
J2 = CON_PCI_75_2199119-4_2230: CON MINIPCI 75POS 0.50MM PITCH FEMALE RT SMD; Chkd/date: ALVY/300521; Crtd /date: ALVY/300521; Custom_Duty: 24%; Customs_HS_Code: 85369090; Distributor_name: DIGIKEY; Distributor_part_number: A115900CT-ND; Footprint Path: Y:\MIS_DATABASE\Library\ALTIUM_TOOL\PCB_FOOTPRINTS\Altium_Footprint_Lib.PcbLib; Height: 3.20MM; Library Path: Y:\MIS_DATABASE\Library\ALTIUM_TOOL\SCHEMATICS_PARTS\MS_CONNECTOR_Library.schlib; Mfr_name: TE CONNECTIVITY; Mfr_part_number: 2199119-4_2230; Mistral Part No: 150021030016-R; Package: SMD; Part_type: CONNECTOR\PCI; Project: VOLTA_CHARGER V5; RoHS: RoHS; Temperature: -40°C+80°C; Tolerance: NA; Voltage: NA; Wattage: NA; Weight: 506mg; Datasheet: Y:\MIS_DATABASE\DATASHEETS\CONNECTORS\2199119.PDF
R1 = RESISTOR: RES 22E 1/20W 1% 0201; Assembly_Instruction: DNI; Chkd/date: PRAVEEN/080922; Crtd /date: TAMILARASU/080922; Custom_Duty: 15%; Customs_HS_Code: 85332119; Distributor_name: DIGIKEY; Distributor_part_number: P122843CT-ND; Footprint Path: Y:\MIS_DATABASE\Library\ALTIUM_TOOL\PCB_FOOTPRINTS\Altium_Footprint_Lib.PcbLib; Height: 0.26MM; Library Path: Y:\MIS_DATABASE\Library\ALTIUM_TOOL\SCHEMATICS_PARTS\MS_DISCRETE_Library.schlib; Mfr_name: PANASONIC-ECG; Mfr_part_number: ERJ-1GNF22R0C; Mistral Part No: 110022090007-R; Package: 0201; Part_type: RESISTORS\FIXED; Project: SK AM62Q LP EVM BRD; RoHS: RoHS; Temperature: -55°C+125°C; Tolerance: 1%; Voltage: NA; Wattage: 1/20W; Weight: 0.15mg; Datasheet: Y:\MIS_DATABASE\DATASHEETS\RESISTORS\PAN-ERJSER_NOV17.PDF
R2 = RESISTOR: RES 0E 1/20W 5% 0201; Chkd/date: NAVEED/301214; Crtd /date: MUDDU/120710; Custom_Duty: 15%; Customs_HS_Code: 85332119; Distributor_name: DIGIKEY; Distributor_part_number: 311-0.0NCT-ND; Footprint Path: Y:\MIS_DATABASE\Library\ALTIUM_TOOL\PCB_FOOTPRINTS\Altium_Footprint_Lib.PcbLib; Height: 0.26MM; Library Path: Y:\MIS_DATABASE\Library\ALTIUM_TOOL\SCHEMATICS_PARTS\MS_DISCRETE_Library.schlib; Mfr_name: YAGEO AMERICA; Mfr_part_number: RC0201JR-070RL; Mistral Part No: 110010070067-R; Package: 0201; Part_type: RESISTORS\FIXED; Project: PB_BUGBASE; RoHS: RoHS; Temperature: -55°C+125°C; Tolerance: 5%; Voltage: NA; Wattage: 1/20W; Weight: 0.17mg; Datasheet: Y:\MIS_DATABASE\DATASHEETS\RESISTORS\RCXXXXL-SER_MAR18.PDF
R261 = RESISTOR: RES 33E 1/20W 5% 0201; Chkd/date: ALVY/070422; Crtd /date: TAMILARASU/070422; Custom_Duty: 15%; Customs_HS_Code: 85332119; Distributor_name: DIGIKEY; Distributor_part_number: P123303CT-ND; Footprint Path: Y:\MIS_DATABASE\Library\ALTIUM_TOOL\PCB_FOOTPRINTS\Altium_Footprint_Lib.PcbLib; Height: 0.26MM; Library Path: Y:\MIS_DATABASE\Library\ALTIUM_TOOL\SCHEMATICS_PARTS\MS_DISCRETE_Library.schlib; Mfr_name: PANASONIC-ECG; Mfr_part_number: ERJ-1GNJ330C; Mistral Part No: 110010070052-R; Package: 0201; Part_type: RESISTORS\FIXED; Project: TI_AM62x_SKEVM_BRD; RoHS: RoHS; Temperature: -55°C+125°C; Tolerance: 5%; Voltage: NA; Wattage: 1/20W; Weight: 0.15mg; Datasheet: Y:\MIS_DATABASE\DATASHEETS\RESISTORS\PAN-ERJSER_NOV17.PDF
R273-R277 = RESISTOR: RES 0E 1/20W 5% 0201; Chkd/date: NAVEED/301214; Crtd /date: MUDDU/120710; Custom_Duty: 15%; Customs_HS_Code: 85332119; Distributor_name: DIGIKEY; Distributor_part_number: 311-0.0NCT-ND; Footprint Path: Y:\MIS_DATABASE\Library\ALTIUM_TOOL\PCB_FOOTPRINTS\Altium_Footprint_Lib.PcbLib; Height: 0.26MM; Library Path: Y:\MIS_DATABASE\Library\ALTIUM_TOOL\SCHEMATICS_PARTS\MS_DISCRETE_Library.schlib; Mfr_name: YAGEO AMERICA; Mfr_part_number: RC0201JR-070RL; Mistral Part No: 110010070067-R; Package: 0201; Part_type: RESISTORS\FIXED; Project: PB_BUGBASE; RoHS: RoHS; SIGNAL_MODEL: RESISTOR_RES0201_0-5_0E_0E; Temperature: -55°C+125°C; Tolerance: 5%; Voltage: NA; Wattage: 1/20W; Weight: 0.17mg; Datasheet: Y:\MIS_DATABASE\DATASHEETS\RESISTORS\RCXXXXL-SER_MAR18.PDF
R281 = RESISTOR: RES 100K 1/10W 1% 0402; Chkd/date: VASANTHA/201216; Crtd /date: MAZHAR/130306; Custom_Duty: 15%; Customs_HS_Code: 85332119; Distributor_name: DIGIKEY; Distributor_part_number: P100KLCT-ND; Footprint Path: Y:\MIS_DATABASE\Library\ALTIUM_TOOL\PCB_FOOTPRINTS\Altium_Footprint_Lib.PcbLib; Height: 0.40MM; Library Path: Y:\MIS_DATABASE\Library\ALTIUM_TOOL\SCHEMATICS_PARTS\MS_DISCRETE_Library.schlib; Mfr_name: PANASONIC-ECG; Mfr_part_number: ERJ-2RKF1003X; Mistral Part No: 110009030187-R; Package: 0402; Part_type: RESISTORS\FIXED; Project: J32; RoHS: RoHS; Temperature: -55°C+155°C; Tolerance: 1%; Voltage: NA; Wattage: 1/10W; Weight: 0.8mg; Datasheet: Y:\MIS_DATABASE\DATASHEETS\RESISTORS\PAN-ERJSER_NOV17.PDF
R282 = RESISTOR: RES 10K 1/20W 1% 0201; Assembly_Instruction: DNI; Chkd/date: VASANTHA/270117; Crtd /date: MANIRAJA/270117; Custom_Duty: 15%; Customs_HS_Code: 85332119; Distributor_name: DIGIKEY; Distributor_part_number: 311-10.0KMCT-ND; Footprint Path: Y:\MIS_DATABASE\Library\ALTIUM_TOOL\PCB_FOOTPRINTS\Altium_Footprint_Lib.PcbLib; Height: 0.26MM; Library Path: Y:\MIS_DATABASE\Library\ALTIUM_TOOL\SCHEMATICS_PARTS\MS_DISCRETE_Library.schlib; Mfr_name: YAGEO AMERICA; Mfr_part_number: RC0201FR-0710KL; Mistral Part No: 110011040018-R; Package: 0201; Part_type: RESISTORS\FIXED; Project: GOLDEN-I LITE; RoHS: RoHS; Temperature: -55°C+125°C; Tolerance: 1%; Voltage: NA; Wattage: 1/20W; Weight: 0.17mg; Datasheet: Y:\MIS_DATABASE\DATASHEETS\RESISTORS\RCXXXXL-SER_MAR18.PDF
R283-R287 R333 = RESISTOR: RES 10K 1/20W 1% 0201; Chkd/date: VASANTHA/270117; Crtd /date: MANIRAJA/270117; Custom_Duty: 15%; Customs_HS_Code: 85332119; Distributor_name: DIGIKEY; Distributor_part_number: 311-10.0KMCT-ND; Footprint Path: Y:\MIS_DATABASE\Library\ALTIUM_TOOL\PCB_FOOTPRINTS\Altium_Footprint_Lib.PcbLib; Height: 0.26MM; Library Path: Y:\MIS_DATABASE\Library\ALTIUM_TOOL\SCHEMATICS_PARTS\MS_DISCRETE_Library.schlib; Mfr_name: YAGEO AMERICA; Mfr_part_number: RC0201FR-0710KL; Mistral Part No: 110011040018-R; Package: 0201; Part_type: RESISTORS\FIXED; Project: GOLDEN-I LITE; RoHS: RoHS; Temperature: -55°C+125°C; Tolerance: 1%; Voltage: NA; Wattage: 1/20W; Weight: 0.17mg; Datasheet: Y:\MIS_DATABASE\DATASHEETS\RESISTORS\RCXXXXL-SER_MAR18.PDF
R581 R582 = RESISTOR: RES 0E 1/20W 5% 0201; Assembly_Instruction: DNI; Chkd/date: NAVEED/301214; Crtd /date: MUDDU/120710; Custom_Duty: 15%; Customs_HS_Code: 85332119; Distributor_name: DIGIKEY; Distributor_part_number: 311-0.0NCT-ND; Footprint Path: Y:\MIS_DATABASE\Library\ALTIUM_TOOL\PCB_FOOTPRINTS\Altium_Footprint_Lib.PcbLib; Height: 0.26MM; Library Path: Y:\MIS_DATABASE\Library\ALTIUM_TOOL\SCHEMATICS_PARTS\MS_DISCRETE_Library.schlib; Mfr_name: YAGEO AMERICA; Mfr_part_number: RC0201JR-070RL; Mistral Part No: 110010070067-R; Package: 0201; Part_type: RESISTORS\FIXED; Project: PB_BUGBASE; RoHS: RoHS; Temperature: -55°C+125°C; Tolerance: 5%; Voltage: NA; Wattage: 1/20W; Weight: 0.17mg; Datasheet: Y:\MIS_DATABASE\DATASHEETS\RESISTORS\RCXXXXL-SER_MAR18.PDF
R595 = RESISTOR: RES 8.2K 1/20W 1% 0201; Chkd/date: SUHAS/230910; Crtd /date: MUDDU/060710; Custom_Duty: 15%; Customs_HS_Code: 85332119; Distributor_name: DIGIKEY; Distributor_part_number: 541-8.20KAABCT-ND; Footprint Path: Y:\MIS_DATABASE\Library\ALTIUM_TOOL\PCB_FOOTPRINTS\Altium_Footprint_Lib.PcbLib; Height: 0.28MM; Library Path: Y:\MIS_DATABASE\Library\ALTIUM_TOOL\SCHEMATICS_PARTS\MS_DISCRETE_Library.schlib; Mfr_name: VISHAY; Mfr_part_number: CRCW02018K20FKED; Mistral Part No: 110010070001-R; Package: 0201; Part_type: RESISTORS\FIXED; Project: PB_BUGBASE; RoHS: RoHS; Temperature: -55°C+155°C; Tolerance: 1%; Voltage: NA; Wattage: 1/20W; Weight: 0.17mg; Datasheet: Y:\MIS_DATABASE\DATASHEETS\RESISTORS\CRCW0201.PDF
U1 = OSC4_ASFL3: OSC 32.768KHz CMOS SMD; Assembly_Instruction: DNI; Chkd/date: ALVY/030620; Crtd /date: MANIRAJA/030620; Custom_Duty: 24%; Customs_HS_Code: 85437099; Distributor_name: DIGIKEY; Distributor_part_number: XC3154CT-ND; Footprint Path: Y:\MIS_DATABASE\Library\ALTIUM_TOOL\PCB_FOOTPRINTS\Altium_Footprint_Lib.PcbLib; Height: 1.00MM; Library Path: Y:\MIS_DATABASE\Library\ALTIUM_TOOL\SCHEMATICS_PARTS\MS_DISCRETE_Library.schlib; Mfr_name: ECS INC; Mfr_part_number: ECS-327MVATX-2-CN-TR; Mistral Part No: 130020060007-R; Package: SMD; Part_type: OSCILLATORS; Project: JETSON_CARRIER_BRD; RoHS: RoHS; Temperature: -40°C+85°C; Tolerance: NA; Voltage: NA; Wattage: NA; Weight: NA; Datasheet: Y:\MIS_DATABASE\DATASHEETS\MISC\CRY_OSC\ECS-327MVATX.PDF
U2 = TXS0102DQX_SON8: IC 2-BIT BI-DIR VOLTAGE-LEVEL TRANSLATOR FOR OPEN-DRAIN AND PUSH-PULL X2SON8; Chkd/date: MANIRAJA/010719; Crtd /date: CHAITHANYA230512; Custom_Duty: 15%; Customs_HS_Code: 85423100; Distributor_name: DIGIKEY; Distributor_part_number: 296-28368-1-ND; Footprint Path: Y:\MIS_DATABASE\Library\ALTIUM_TOOL\PCB_FOOTPRINTS\Altium_Footprint_Lib.PcbLib; Height: 0.40MM; Library Path: Y:\MIS_DATABASE\Library\ALTIUM_TOOL\SCHEMATICS_PARTS\MS_MISCINTERFACE_Library.schlib; Mfr_name: TEXAS INSTRUMENTS; Mistral Part No: 141012050010-R; Package: X2SON8; Part_type: ICS\INTERFACE\LEVEL TRANSLATOR; Project: GEN_3-8_DB; RoHS: RoHS; Temperature: -40°C+85°C; Tolerance: NA; Voltage: NA; Wattage: NA; Weight: 1.2mg; Datasheet: Y:\MIS_DATABASE\DATASHEETS\ICS\INTERFACE\TXS0102-SER.PDF

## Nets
DGND: C3.1 C5.2 C7.1 C25.2 C26.2 C27.2 C28.2 C31.2 C32.2 C33.2 C34.1 C35.2 C36.2 C37.2 C42.2 C71.2 C75.2 C86.2 C176.1 C177.2 C188.1 C189.2 C225.2 C226.2 C234.2 C235.2 C236.2 C237.2 C238.2 C239.2 C240.2 C241.2 C242.2 C244.2 C246.2 C247.2 C248.2 C249.2 C252.2 C253.2 C254.2 C255.2 C256.2 C257.2 C258.2 C259.2 C260.1 C261.2 C262.2 C263.2 C264.2 C265.2 C266.2 C267.2 C268.2 C269.2 C270.2 C271.2 C272.2 C273.2 C274.2 C275.2 C277.2 C278.2 C279.2 C281.2 C282.2 C284.2 C285.2 C286.2 C287.2 C288.2 C289.2 C290.2 C291.2 C292.2 C293.2 C294.2 C295.2 C296.2 C297.2 C298.2 C299.2 C300.2 C301.2 C302.2 C303.2 C304.2 C305.1 C306.2 C307.2 C308.2 C309.2 C310.2 C311.2 C314.2 C316.2 C327.2 C328.2 C329.2 C348.2 C349.2 C507.2 C531.2 C533.2 J2.1(GND) J2.7(GND) J2.18(GND) J2.33(GND) J2.39(GND) J2.45(GND) J2.51(GND) J2.57(GND) J2.63(GND) J2.69(GND) J2.75(GND) J2.SH1 J2.SH2 R5.1 R115.2 R281.1 U1.2(GND) U2.4(GND) U12.A1(VSS) U12.A4(VSS) U12.A21(VSS) U12.AA1(VSS) U12.AA9(VSS) U12.AA12(VSS) U12.AA15(VSS) U12.AA21(VSS) U12.D4(VSS) U12.D11(VSS) U12.D19(VSS) U12.E2(VSS) U12.F4(VSS) U12.F9(VSS) U12.F11(VSS) U12.F13(VSS) U12.F15(VSS) U12.G6(VSS) U12.G9(VSS) U12.G16(VSS) U12.H1(VSS) U12.H6(VSS) U12.H13(VSS) U12.J6(VSS) U12.J10(VSS) U12.J12(VSS) U12.J14(VSS) U12.J16(VSS) U12.K3(VSS) U12.K6(VSS) U12.K8(VSS) U12.K13(VSS) U12.L1(VSS) U12.L6(VSS) U12.L10(VSS) U12.L12(VSS) U12.L14(VSS) U12.L16(VSS) U12.M6(VSS) U12.M9(VSS) U12.M11(VSS) U12.M16(VSS) U12.M18(VSS) U12.N6(VSS) U12.N12(VSS) U12.N14(VSS) U12.P1(VSS) U12.P3(VSS) U12.P6(VSS) U12.P10(VSS) U12.P13(VSS) U12.P15(VSS) U12.P16(VSS) U12.R5(VSS) U12.R7(VSS) U12.R8(VSS) U12.R16(VSS) U12.T3(VSS) U12.T6(VSS) U12.T7(VSS) U12.T9(VSS) U12.T10(VSS) U12.T12(VSS) U12.T15(VSS) U12.U5(VSS) U12.U8(VSS) U12.U10(VSS) U12.U13(VSS) U12.V11(VSS) U12.V14(VSS) U12.V19(VSS) U12.W7(VSS) U12.W10(VSS) U12.W13(VSS) U12.Y3(VSS) U12.Y4(VSS) U12.Y6(VSS) U12.Y11(VSS) U12.Y14(VSS) U125.A1(GND) ; also on sheet 1 2 3 4 13 14 15 16 20 21 22 23 24 25 26 27 28 29 30 31 32 33 34 35 36 37 38 39 40 41 42 43
VCC1V8_SYS: C3.2 R262.2 R282.2 R283.2 R284.2 R285.2 R286.2 R287.2 R333.2 R582.1 U2.1(VCCA) ; also on sheet 4 16 20 22 25 34 37 39 40 42
VCC_3V3_MAIN: C531.1 FL14.1 R387.1 R586.1 U125.B2(VIN) ; also on sheet 4 15
VCC_3V3_SYS: C7.2 C176.2 C177.1 C188.2 C189.1 J2.2(3-3V) J2.4(3-3V) J2.72(3-3V) J2.74(3-3V) R257.2 R258.2 R279.2 R581.1 U2.8(VCCB) ; also on sheet 1 4 15 16 20 21 23 24 26 27 29 30 31 32 33 34 36 37 38 39 40 41 42 43
VDD_CANUART: C42.1 C302.1 C311.1 R587.2 U12.H8(VDD_CANUART)
VDD_CANUART_EN: R586.2 U125.A2(EN) ; also on sheet 4
VDD_CORE: C26.1 C27.1 C32.1 C241.1 C242.1 C249.1 C253.1 C254.1 C256.1 C258.1 C262.1 C263.1 C264.1 C268.1 C269.1 C271.1 C273.1 C274.1 C282.1 C285.1 C286.1 C292.1 C297.1 C303.1 FL15.2 U12.H12(VDD_CORE) U12.H14(VDD_CORE) U12.J9(VDD_CORE) U12.J11(VDD_CORE) U12.J13(VDD_CORE) U12.K10(VDD_CORE) U12.K14(VDD_CORE) U12.L11(VDD_CORE) U12.L13(VDD_CORE) U12.M8(VDD_CORE) U12.M12(VDD_CORE) U12.M14(VDD_CORE) U12.N9(VDD_CORE) U12.N11(VDD_CORE) U12.N13(VDD_CORE) U12.P8(VDD_CORE) U12.P11(VDDA_CORE_USB) U12.P12(VDDA_CORE_CSIRX0) ; also on sheet 16
VDD_LPDDR4: C298.1 C301.1 C308.1 C309.1 C314.1 C316.1 C348.1 C349.1 U12.C1(VDDS_DDR) U12.J8(VDDS_DDR) U12.K7(VDDS_DDR) U12.K9(VDDS_DDR) U12.L7(VDDS_DDR_C) U12.L8(VDDS_DDR) U12.U1(VDDS_DDR) ; also on sheet 3 16
VDDA_1V8: C277.1 FL3.1 FL4.1 FL12.1 U12.R11(VDDA_1P8_USB) ; also on sheet 16
VDDA_1V8_FB1: C225.1 C226.1 C235.1 C255.1 C265.1 C281.1 C287.1 C307.1 FL12.2 U12.F16(VDDA_TEMP1) U12.H10(VDDA_MCU) U12.K12(VDDA_PLL2) U12.M7(VDDA_TEMP0) U12.N10(VDDA_PLL0) U12.P14(VDDA_PLL1)
VDDA_1V8_FB2: C28.1 C31.1 C275.1 C296.1 C299.1 FL3.2 U12.P9(VDDA_1P8_OLDI0) U12.R9(VDDA_1P8_OLDI0) U12.R12(VDDA_1P8_CSIRX0)
VDDA_1V8_FB_OSC: C25.1 C306.1 FL4.2 U12.J7(VDDS_OSC0)
VDDA_DDR_PLL0: C295.1 C329.1 FL15.1 U12.L9(VDDA_DDR_PLL0)
VDDA_SYS_MON: C533.1 R115.1 R387.2 U12.F6(VMON_VSYS)
VDDR_CORE: C33.1 C34.2 C35.1 C36.1 C37.1 C270.1 C288.1 C294.1 U12.H11(VDDR_CORE) U12.M10(VDDR_CORE) U12.M13(VDDR_CORE) ; also on sheet 16 36
VDDSHV_CANUART: C310.1 C327.1 C328.1 FL14.2 U12.G7(VDDSHV_CANUART) U12.H7(VDDSHV_CANUART) ; also on sheet 2 4 31 32
VDDSHV_SDIO: FL9.1 ; also on sheet 4 21
BT_EN_SOC: J2.54(W_DISABLE2#) R258.1 ; also on sheet 34
BT_UART_WAKE_SOC: J2.20(UART_WAKE#) R279.1 ; also on sheet 39
CAP_VDDS0: C284.1 U12.G12(CAP_VDDS0)
CAP_VDDS1: C234.1 U12.L15(CAP_VDDS1)
CAP_VDDS2: C266.1 U12.R13(CAP_VDDS2)
CAP_VDDS3: C240.1 U12.M15(CAP_VDDS3)
CAP_VDDS4: C304.1 U12.N8(CAP_VDDS4)
CAP_VDDS5: C246.1 U12.G15(CAP_VDDS5)
CAP_VDDS6: C239.1 U12.J15(CAP_VDDS6)
CAP_VDDS_CANUART: C300.1 U12.G8(CAP_VDDS_CANUART)
CAP_VDDS_MCU: C278.1 U12.G11(CAP_VDDS_MCU)
COM_SDIO_CMD: J2.11(SDIO_CMD) R275.1 R285.1
COM_SDIO_D0: J2.13(SDIO_DATA0) R277.1 R287.1
COM_SDIO_D1: J2.15(SDIO_DATA1) R276.1 R286.1
COM_SDIO_D2: J2.17(SDIO_DATA2) R274.1 R284.1
COM_SDIO_D3: J2.19(SDIO_DATA3) R273.1 R283.1
HFOSC0_CLKOUT_32K: R2.1 ; also on sheet 32
M2_LED1#: J2.6(LED_1#) TP94.1(TP)
M2_LED2#: J2.16(LED_2#) TP93.1(TP)
MCASP1_ACLKX_BT: J2.8(PCM_CLK/I2S_SCK) ; also on sheet 39
MCASP1_AFSX_BT: J2.10(PCM_SYNC/I2S_WS) ; also on sheet 39
MCASP1_AXR0_BT: J2.12(PCM_IN/I2S_SD_IN) R281.2 ; also on sheet 39
MCASP1_AXR2_BT: J2.14(PCM_OUT/I2S_SD_OUT) ; also on sheet 39
MMC2_CLK: J2.9(SDIO_CLK/SYSCLK) R282.1 ; also on sheet 20
MMC2_CMD: R275.2 ; also on sheet 20
MMC2_D0: R277.2 ; also on sheet 20
MMC2_D1: R276.2 ; also on sheet 20
MMC2_D2: R274.2 ; also on sheet 20
MMC2_D3: R273.2 ; also on sheet 20
SLOW_CLK: J2.50(SUSCLK_32kHz) R1.2 R2.2
SOC_DVDD1V8: C86.1 C237.1 C238.1 C248.1 C293.1 C305.2 U12.H9(VMON_1P8_SOC) U12.H15(VDDSHV6) U12.H16(VDDSHV6) U12.K15(VDDSHV1) U12.K16(VDDSHV1) U12.N7(VDDSHV4) U12.P7(VDDSHV4) ; also on sheet 3 16
SoC_DVDD3V3: C71.1 C75.1 C236.1 C244.1 C247.1 C252.1 C259.1 C260.2 C261.1 C267.1 C272.1 C279.1 C289.1 C290.1 C291.1 U12.F10(VDDSHV_MCU) U12.F12(VDDSHV0) U12.G10(VDDSHV_MCU) U12.G13(VDDSHV0) U12.K11(VMON_3P3_SOC) U12.N15(VDDSHV3) U12.N16(VDDSHV3) U12.R10(VDDA_3P3_USB) U12.R14(VDDSHV2) U12.R15(VDDSHV2) ; also on sheet 16
SOC_UART1_CTS_BT: J2.34(UART_CTS) ; also on sheet 37
SOC_UART1_RTS_BT: J2.36(UART_RTS) ; also on sheet 37
SOC_UART1_RX_BT: J2.22(UART_RXD) ; also on sheet 37
SOC_UART1_TX_BT: R261.2 ; also on sheet 37
SoC_VDDSHV5_SDIO: C257.1 FL9.2 U12.F14(VDDSHV5) U12.G14(VDDSHV5)
SoC_WLAN_SDIO_RST: U2.7(B1) ; also on sheet 39
TEMP_DIODE_P: TP21.1(TP) U12.F8(RSVD3)
USB_DM: J2.5(USB_D-) TP95.1(TP)
USB_DP: J2.3(USB_D+) TP96.1(TP)
VPP_1V8: U12.F7(VPP) ; also on sheet 15
WL_LT_EN: R595.1 ; also on sheet 39
WLAN_EN: J2.56(W_DISABLE1#) R257.1 U2.6(B2)
WLAN_EN_SOC: U2.3(A2) ; also on sheet 20
WLAN_IRQ: J2.62(ALERT#) R333.1 ; also on sheet 20
WLAN_SDIO_RST: J2.23(SDIO_RESET#/TX_BLANKING) R262.1 U2.2(A1)
N15951745: C5.1 R581.2 R582.2 U1.1(TRI-STATE) U1.4(VDD)
N15952254: R1.1 U1.3(OUTPUT)
N21029653: R5.2 R595.2 U2.5(OE)
N21608525: J2.32(UART_TXD) R261.1
N22163762: C507.1 R587.1 U125.B1(VOUT)

Not connected (* = marked no-connect by the designer): J2 21(SDIO_WAKE#)* 35(PETP0)* 37(PETN0)* 38(VENDOR_DEFINED1)* 40(VENDOR_DEFINED2)* 41(PERP0)* 42(VENDOR_DEFINED3)* 43(PERN0)* 44(COEX3)* 46(COEX_RXD)* 47(REFCLKP0)* 48(COEX_TXD)* 49(REFCLKN0)* 52(PERST0#)* 53(CLKREQ0#)* 55(PEWAKE0#)* 58(I2C_DATA)* 59(RESERVED/PETP1)* 60(I2C_CLK)* 61(RESERVED/PETN1)* 64(RESERVED)* 65(RESERVED/PERP1)* 66(UIM_SWP/PERST1#)* 67(RESERVED/PERN1)* 68(UIM_POWER_SNK/CLKREQ1#)* 70(UIM_POWER_SRC/GPIO1/PEWAKE#)* 71(RESERVED/REFCLKP1)* 73(RESERVED/REFCLKN1)* SH3*

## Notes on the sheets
sheet 17
- D-Note :-
  Recommend implementing the voltage monitoring functionality using VMON_VSYS
  for early detection of supply failure
  It is meant to be a  power-fail indicator for the main input (higher)
  voltage rail that enters the PCB.  For example, 5, 12, or 24 volts.
  The error associated with this monitor would require you to set the threshold
  significantly lower than the nominal to avoid false trigger
  Refer System Power Supply Monitor Design Guidelines section of the data sheet
- SOC POWER
- 0.5V to VMON_ER_SYS pin
- D-Note :-
  Changing the core voltage is not
  allowed after the device has been
  released from reset. If you turn
  off the core supply, we expect
  you to turn off all power rails
  and ramp them down per the
  power-down sequence and wait
  until all supply rails decay
  below 300mv before turning on
  power again.
- D-Note :- VDD_CORE and VDDR_CORE
  are recommended to be powered by the
  same source so they ramp together
  when VDD_CORE is operating at 0.85V
- D-Note :-
  Select cap with less the 1 ohm ESR
  Ensure the PCB loop inductance is < 2.5 nH
  Select 0201 package or smallest possible package
  Refer SoC Data sheet
- D-Note :-
  Common SOC LVCMOS IO interface guidelines
  1. Most of the SOC IOs are not fail-safe. No input should be applied before supply ramps.
  2. SOC LVCMOS inputs have minimum slew rate requirements specified
  3. SOC IO buffers are off during Reset. A pull is required near to the attached device
  being driven by the SOC IOs
  4. Any SOC IO that has a trace connected  and not being actively driven needs a parallel
  pull. When adding pull is not feasible, ensure the traces are routed away from noisy
  signals
- CAD NOTE: Pin H9 (VMON_1P8_SOC) needs to be routed
   as a signal line and connect to a quiet supply location such
   as after decoupling caps after the DC/DC and before the
   multi-supply branching.
- D-Note :-
  A Trace connected to SOC  is effectively an antenna that will pick up noise.
  A potential will be generated on the signal when noise couples into the antenna.  This
  potential will be largest on the highest impedance end of the signal.
  By placing a pull-up or pull-down near the SoC pin, we force the highest potential to the
  open-circuit end of the signal rather than the SoC end of the signal.
- R-Note
  Connecting 1.8V supply source
  directly to VPP continuously is
  not allowed
- R-Note:- Reserved pin
  Leave unconnected
- D-Note :-
  Refer pin connectivity table of the SOC data sheet for connecting the USB IO, analog and core supplies
  when USB interface is not used.
  It is acceptable to have the supplies connected and all the USB pins left unconnected provided the USB
  driver is not initialized any time and the USB calibration procedure does not happen.
  Grounding the USB supplies as per pin connectivity requirements when not used saves power when low power
  is a critical requirement.
- D-Note :-
  Refer Pin connectivity requirements to connect the CSI0
  supplies (analog and core) when CSI0 interface is not used
  Ferrite and Bulk Caps are optional when CSI0 is not used and
  Boundary scan functionality is required
- CORE SUPPLY
- U8Q.J7 = VDDS_OSC
- U8Q.L9 = VDDA_DDR_PLL0
- U8Q.P8 = VDDA_CORE_USB
- 1.8V Analog SUPPLY
- U8Q.R11 = VDDA_1V8_CSIRX
- U8Q.P7,R7 = VDDA_1V8_OLDI
- U8Q.P10 = VDDA_CORE_CSI
- U8Q.R8 = VDDA_1V8_USB
- U8Q.N9 = VDDA_PLL0
- U8Q.P14 = VDDA_PLL1
- U8Q.H10 = VDDA_1V8_MCU
- U8Q.J13 = VDDA_PLL2
- U8Q.P6 = VDDA_TEMP0
  U8Q.F16 = VDDA_TEMP1
- VDD_CANUART
- U8Q.H8 = VDD_CANUART
- U8Q.G7, U8Q.H7   = VDDSHV_CANUART
- 3.3V/1.8V MMC1 SUPPLY
- D-Note :-
  Add a bulk cap 1 uF  to minimize
  resonance
- BLM15PX121SN1D :- 120E
  2A @ 85 deg C
  1.1A @ 125 deg C
sheet 18
- SOC POWER SUPPLIES - DECAPS
- CAD Note:- Place 0.1 uF caps near to SoC pins
- CAD Note:- Place 0.1 uF caps near to SoC pins
- CAD Note:- Place 0.1 uF caps near to SoC pins
- CAD Note:- Place 0.1 uF caps near to SoC pins
- CAD Note:- Place 0.1 uF caps near to SoC pins
- SOC VSS
sheet 19
- M.2 INTERFACE - SDIO
- As per the connector specification
  1 Amps will support per pin
- 1.8 V
- 1.8 V
- 3.3 V
- SoC_MAIN_UART1_RXD
- 1.8 V
- SoC_MAIN_UART1_TXD
- SoC_MAIN_UART1_CTS
- SoC_MAIN_UART1_RTS
- 3.3V
- 3.3 V
- 1.8 V
- D-Note :-
  Add a bulk cap when oscillator is used
- WILINK LEVEL TRANSLATORS
- D-Note :-
  Ok to use 10K, 5%
- CAD Note:-
  Place R1 & R2 close
  to each other to
  avoid stub.
- Design Note: WL_LT_EN = Active High
